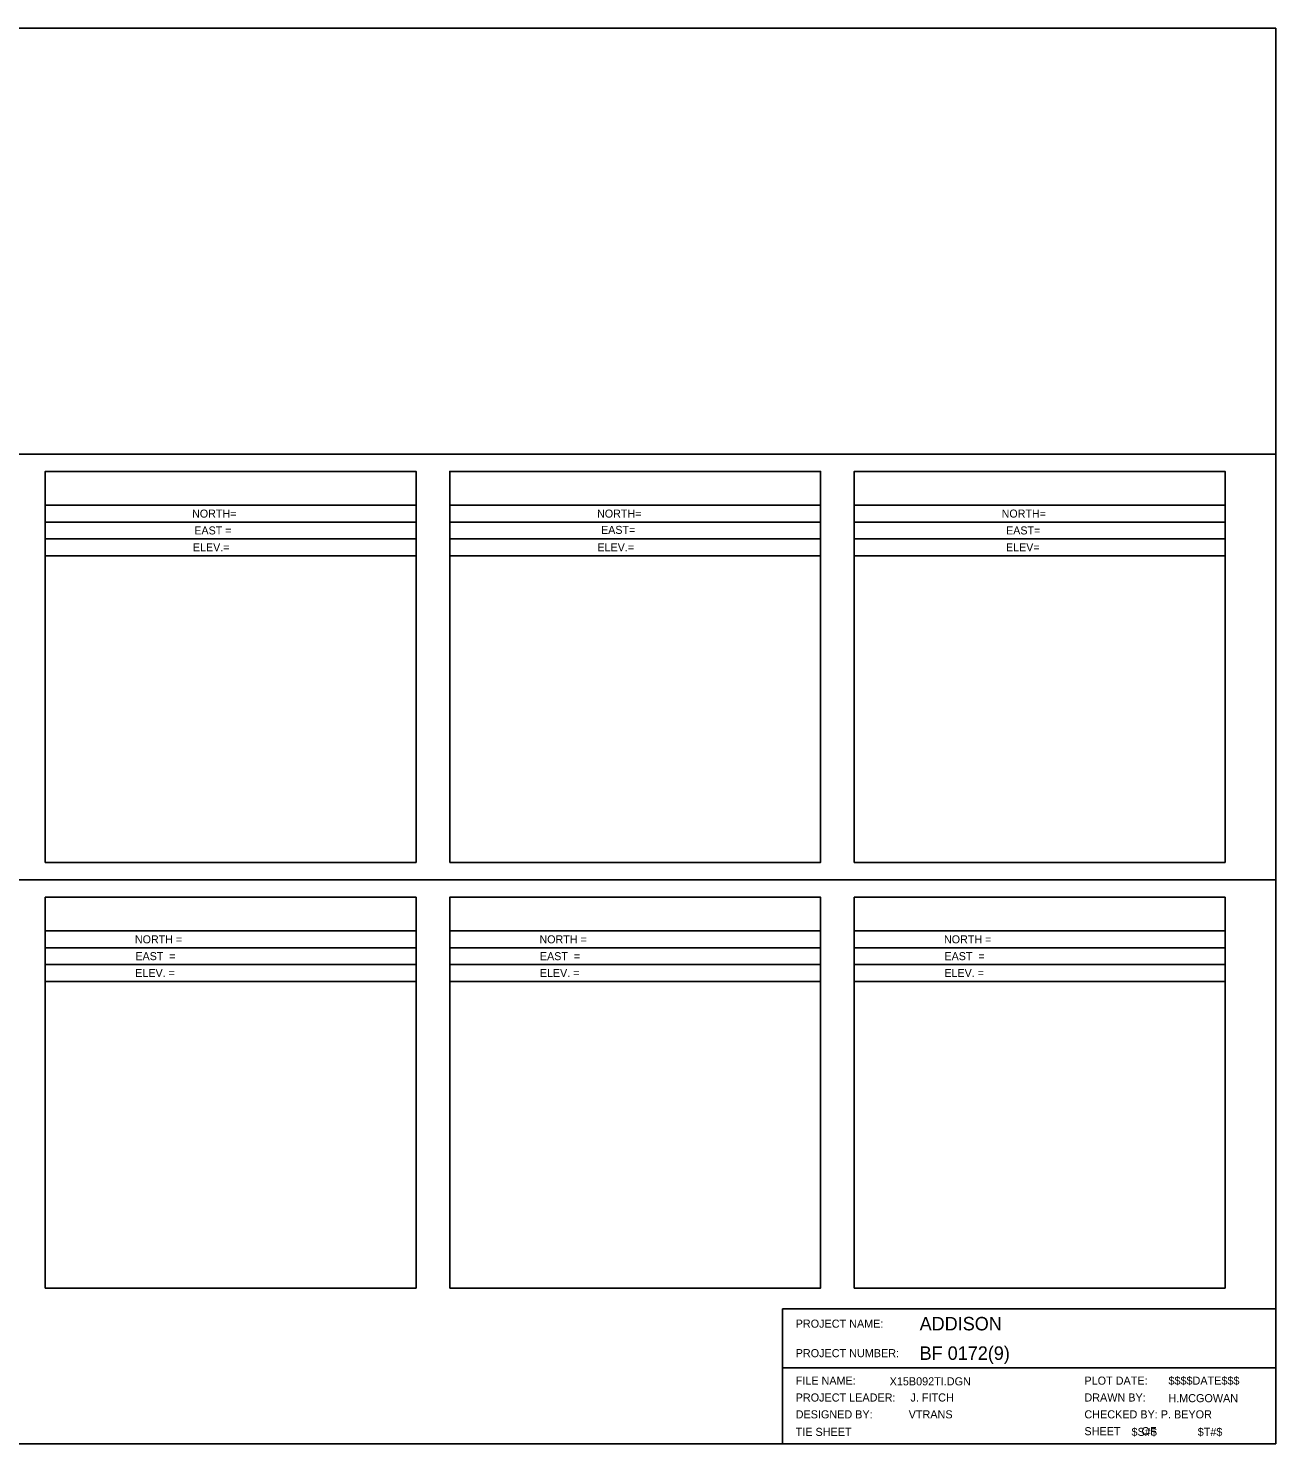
# Model space of a CAD drawing. Extents: x 1514039 to 1514679, y 870735 to 871155.
# Drawn here: x 1514308.6 to 1514678.6, y 870735.2 to 871155.2 of the extents above; entities that cross this region are included whole.
import ezdxf

# ---------------------------------------------------------------- set-up
doc = ezdxf.new("R2010")
doc.units = 0
doc.layers.add('NBL1', color=7, linetype='Continuous')
doc.layers.add('NBL2', color=7, linetype='Continuous')

msp = doc.modelspace()

# ---------------------------------------------------------------- linework, layer by layer
at = {"layer": 'NBL1'}
msp.add_line((1514532.32, 870757.72), (1514678.57, 870757.72), dxfattribs=at)
msp.add_lwpolyline([(1514038.57, 870735.22), (1514678.57, 870735.22), (1514678.57, 871155.22), (1514038.57, 871155.22)], close=True, dxfattribs=at)
msp.add_lwpolyline([(1514678.57, 870775.22), (1514532.32, 870775.22), (1514532.32, 870735.22)], dxfattribs=at)
at = {"layer": 'NBL2'}
for p, q in [((1514038.57, 871028.89), (1514678.57, 871028.89)), ((1514423.57, 871013.72), (1514313.57, 871013.72)), ((1514543.57, 871013.72), (1514433.57, 871013.72)), ((1514663.57, 871013.72), (1514553.57, 871013.72)), ((1514423.57, 871008.72), (1514313.57, 871008.72)), ((1514543.57, 871008.72), (1514433.57, 871008.72)), ((1514663.57, 871008.72), (1514553.57, 871008.72)), ((1514423.57, 871003.72), (1514313.57, 871003.72)), ((1514439.32, 871003.72), (1514433.57, 871003.72)), ((1514538.96, 871003.72), (1514439.32, 871003.72)), ((1514543.57, 871003.72), (1514538.96, 871003.72)), ((1514663.57, 871003.72), (1514553.57, 871003.72)), ((1514423.57, 870998.72), (1514313.57, 870998.72)), ((1514439.32, 870998.72), (1514433.57, 870998.72)), ((1514538.96, 870998.72), (1514439.32, 870998.72)), ((1514543.57, 870998.72), (1514538.96, 870998.72)), ((1514663.57, 870998.72), (1514553.57, 870998.72)), ((1514038.57, 870902.55), (1514678.57, 870902.55)), ((1514423.57, 870887.39), (1514313.57, 870887.39)), ((1514543.57, 870887.39), (1514433.57, 870887.39)), ((1514663.57, 870887.39), (1514553.57, 870887.39)), ((1514423.57, 870882.39), (1514313.57, 870882.39)), ((1514543.57, 870882.39), (1514433.57, 870882.39)), ((1514663.57, 870882.39), (1514553.57, 870882.39)), ((1514423.57, 870877.39), (1514313.57, 870877.39)), ((1514543.57, 870877.39), (1514433.57, 870877.39)), ((1514663.57, 870877.39), (1514553.57, 870877.39)), ((1514423.57, 870872.39), (1514313.57, 870872.39)), ((1514543.57, 870872.39), (1514433.57, 870872.39)), ((1514663.57, 870872.39), (1514553.57, 870872.39))]:
    msp.add_line(p, q, dxfattribs=at)
for points in [[(1514313.57, 870907.72), (1514423.57, 870907.72), (1514423.57, 871023.72), (1514313.57, 871023.72)], [(1514433.57, 870907.72), (1514543.57, 870907.72), (1514543.57, 871023.72), (1514433.57, 871023.72)], [(1514553.57, 870907.72), (1514663.57, 870907.72), (1514663.57, 871023.72), (1514553.57, 871023.72)], [(1514313.57, 870781.39), (1514423.57, 870781.39), (1514423.57, 870897.39), (1514313.57, 870897.39)], [(1514433.57, 870781.39), (1514543.57, 870781.39), (1514543.57, 870897.39), (1514433.57, 870897.39)], [(1514553.57, 870781.39), (1514663.57, 870781.39), (1514663.57, 870897.39), (1514553.57, 870897.39)]]:
    msp.add_lwpolyline(points, close=True, dxfattribs=at)

# ---------------------------------------------------------------- texts
at = {"layer": 'NBL1'}
for s, height, p in [('PROJECT NAME:', 2.4, (1514536.19, 870769.64)), ('ADDISON', 4, (1514572.96, 870768.84)), ('PROJECT NUMBER:', 2.4, (1514536.19, 870760.89)), ('BF 0172(9)', 4, (1514572.96, 870760.09)), ('FILE NAME:', 2.4, (1514536.19, 870752.73)), ('       X15B092TI.DGN', 2.4, (1514557.82, 870752.53)), ('PLOT DATE:', 2.4, (1514621.84, 870752.73)), ('$$$$DATE$$$', 2.4, (1514646.77, 870752.73)), ('PROJECT LEADER:     J. FITCH', 2.4, (1514536.19, 870747.73)), ('DRAWN BY:', 2.4, (1514621.84, 870747.73)), ('H.MCGOWAN    ', 2.4, (1514646.74, 870747.53)), ('DESIGNED BY:            VTRANS', 2.4, (1514536.19, 870742.73)), ('CHECKED BY: P. BEYOR ', 2.4, (1514621.84, 870742.73)), ('TIE SHEET ', 2.4, (1514536.19, 870737.53)), ('SHEET       OF', 2.4, (1514621.84, 870737.73)), ('$S#$ ', 2.4, (1514635.82, 870737.53)), ('$T#$   ', 2.4, (1514655.44, 870737.53))]:
    msp.add_text(s, height=height, dxfattribs=at).set_placement(p)
at = {"layer": 'NBL2'}
for s, p in [('NORTH=', (1514357.15, 871010.03)), ('NORTH=', (1514477.28, 871010.03)), ('NORTH=', (1514597.28, 871010.03)), ('EAST =', (1514357.81, 871005.03)), ('EAST=', (1514478.46, 871005.19)), ('EAST=', (1514598.6, 871005.03)), ('ELEV.=', (1514357.39, 871000.03)), ('ELEV.=', (1514477.39, 871000.03)), ('ELEV=', (1514598.57, 871000.03)), ('NORTH =             ', (1514340.19, 870883.7)), ('NORTH =             ', (1514460.19, 870883.7)), ('NORTH =             ', (1514580.19, 870883.7)), ('EAST  =             ', (1514340.33, 870878.7)), ('EAST  =             ', (1514460.33, 870878.7)), ('EAST  =             ', (1514580.33, 870878.7)), ('ELEV. =             ', (1514340.3, 870873.7)), ('ELEV. =             ', (1514460.3, 870873.7)), ('ELEV. =             ', (1514580.3, 870873.7))]:
    msp.add_text(s, height=2.375, dxfattribs=at).set_placement(p)

doc.saveas('drawing.dxf')
